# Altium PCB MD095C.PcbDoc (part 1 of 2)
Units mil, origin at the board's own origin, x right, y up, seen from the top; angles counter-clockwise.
Board outline 4500 x 5500 mil, 6 copper layers (Top Layer, Kelvin, MidLayer2, GND, InternalPlane2, Bottom Layer); 145 components, 65 nets, 384 pads, 258 vias.
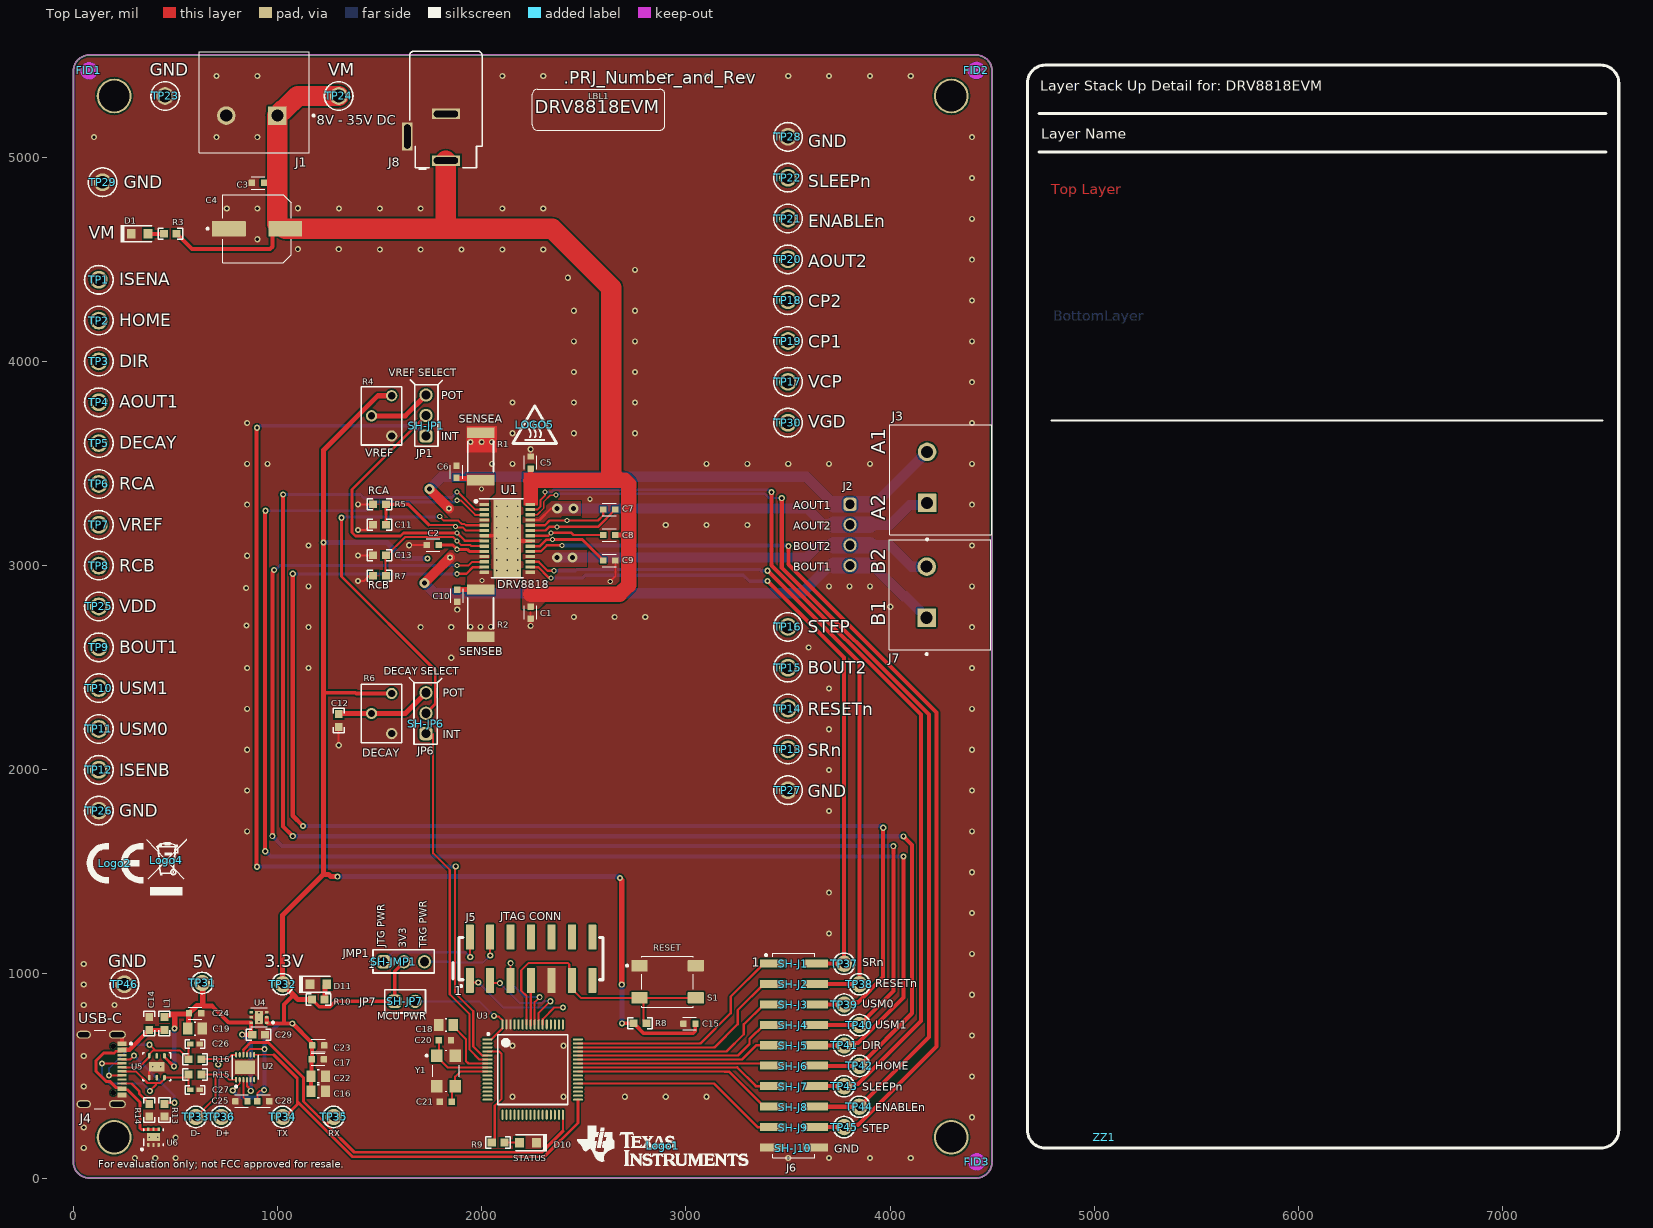
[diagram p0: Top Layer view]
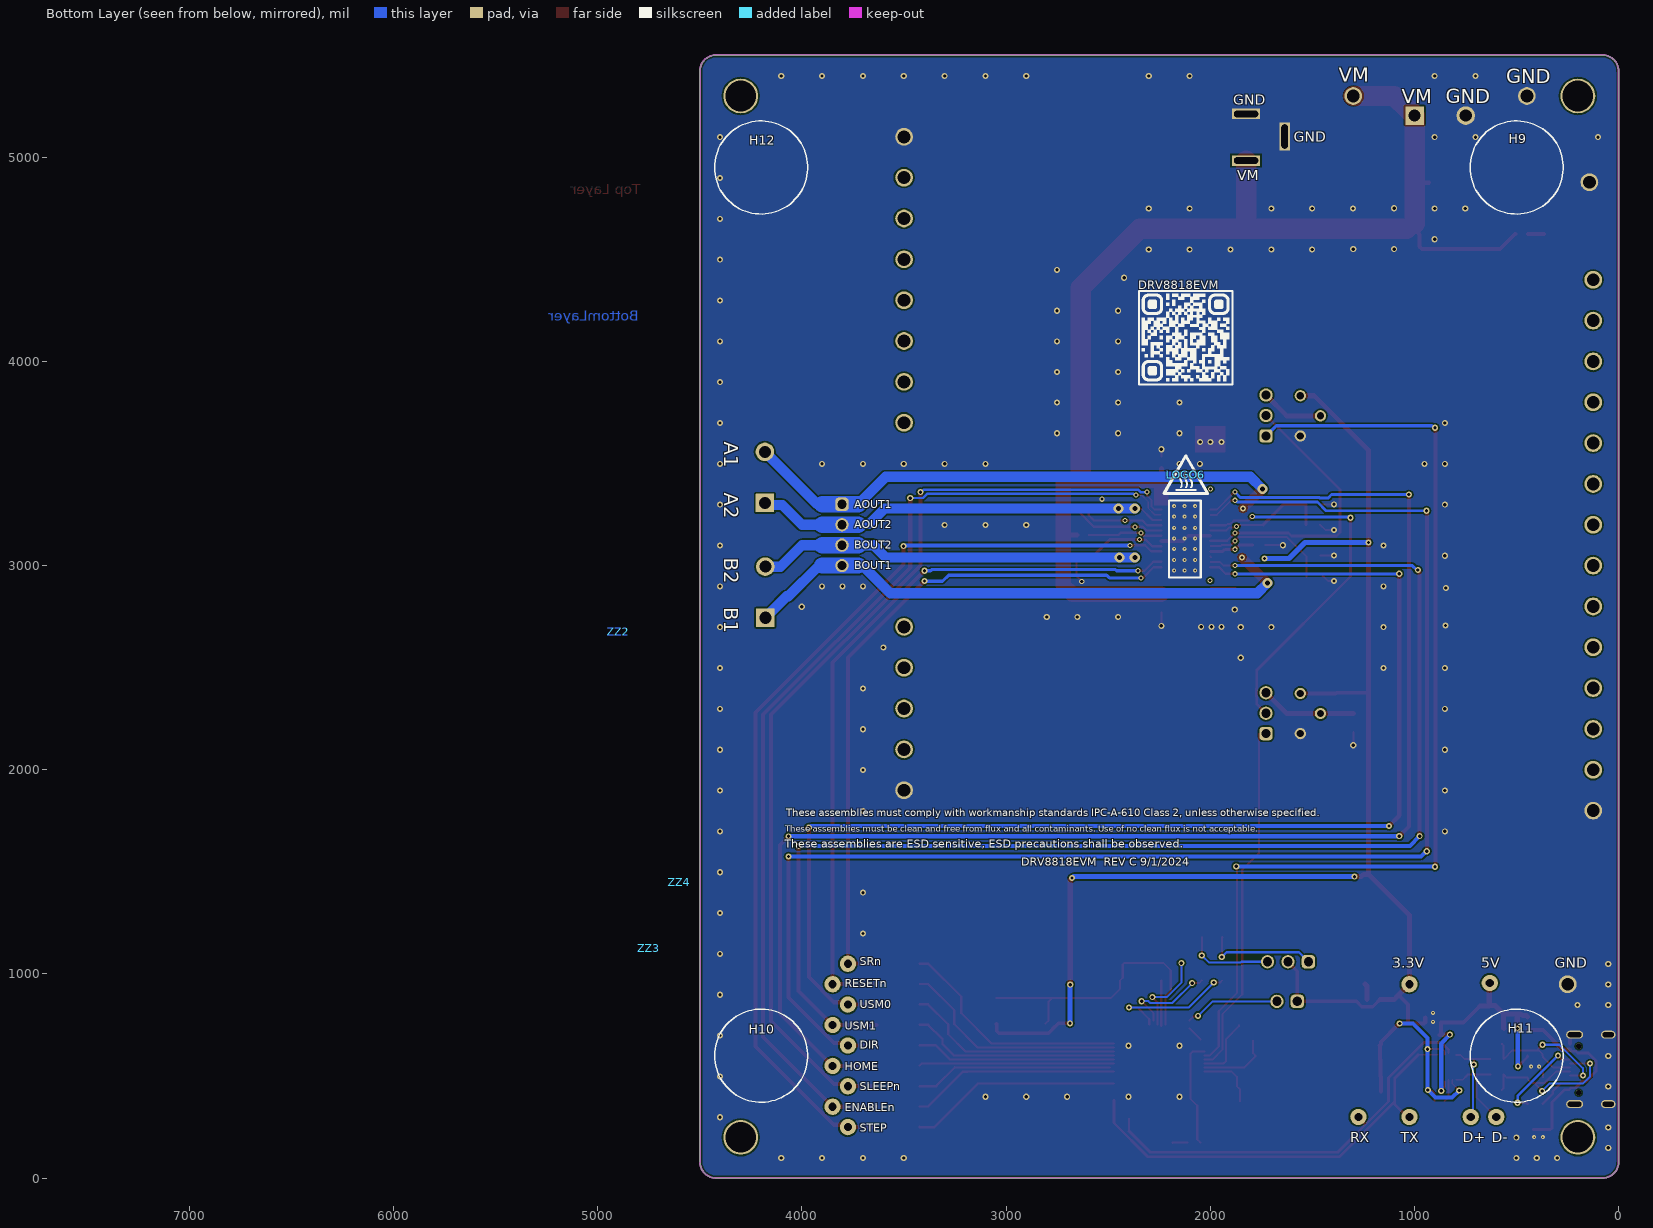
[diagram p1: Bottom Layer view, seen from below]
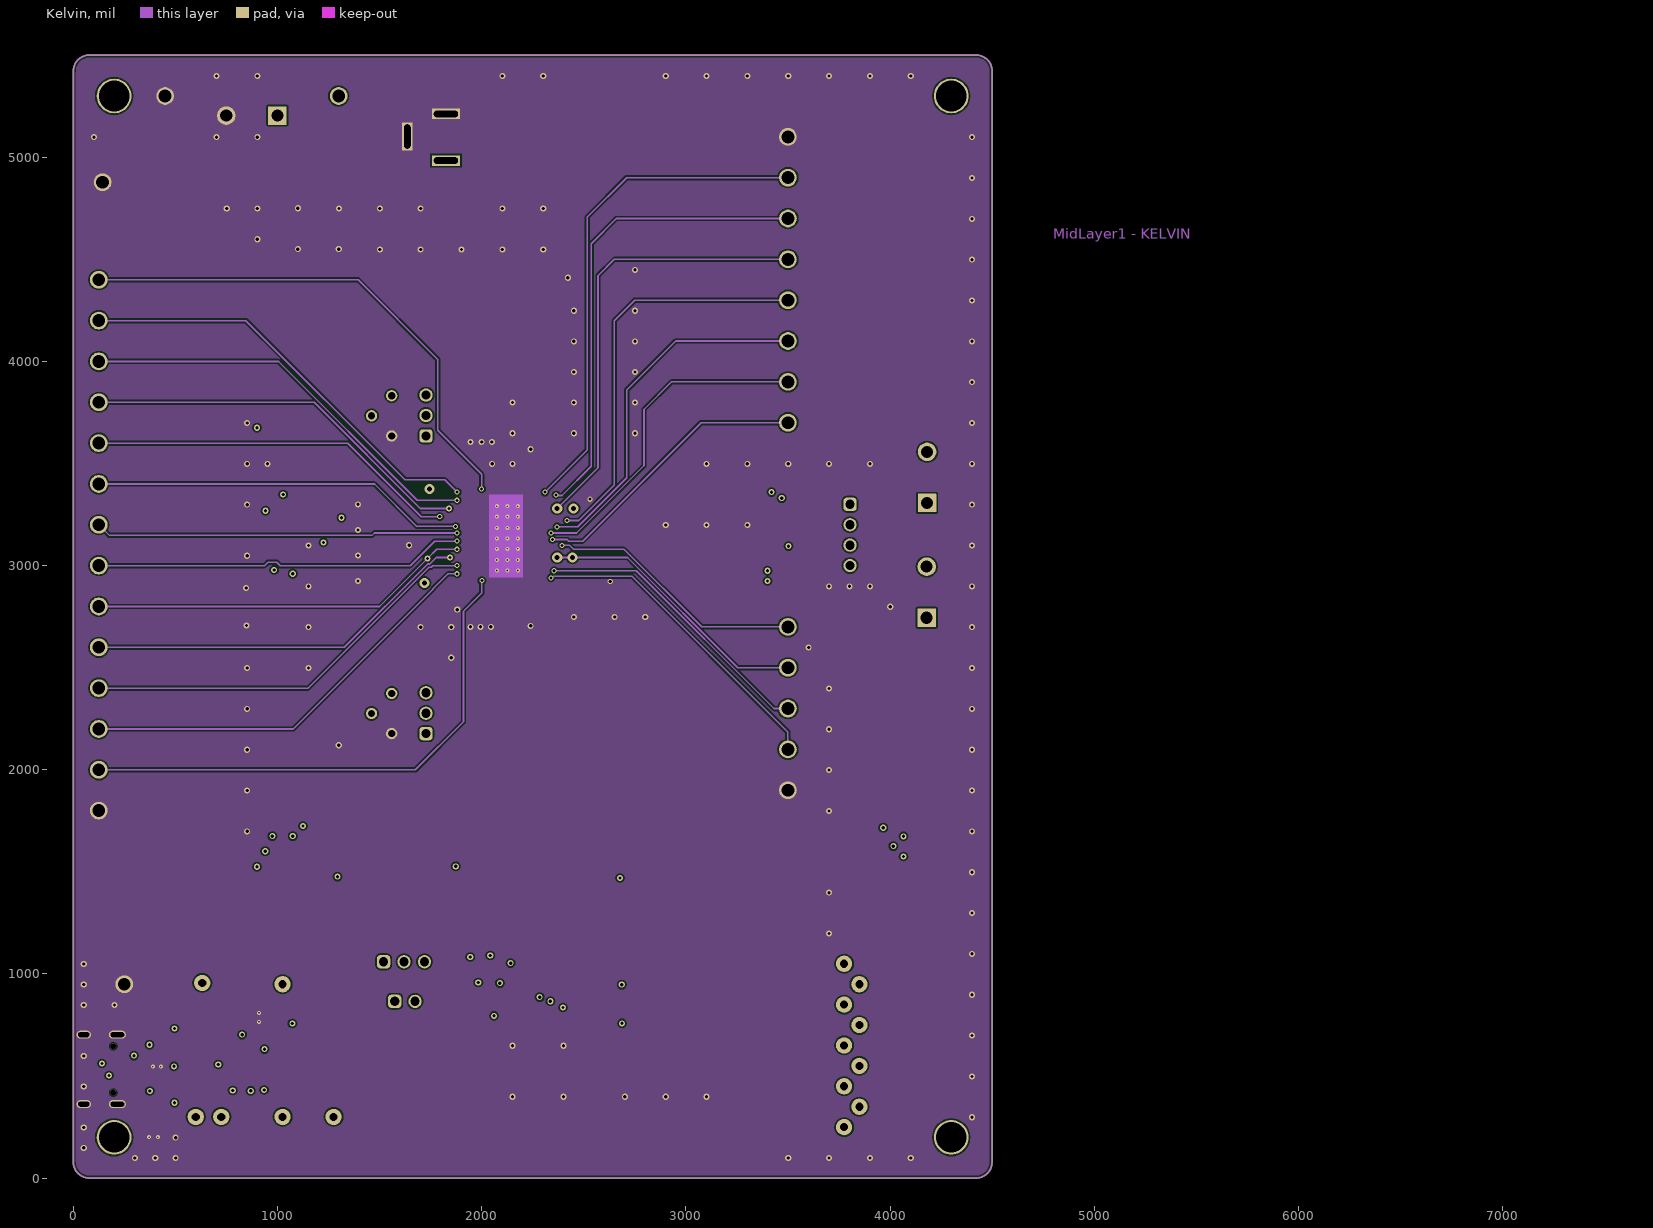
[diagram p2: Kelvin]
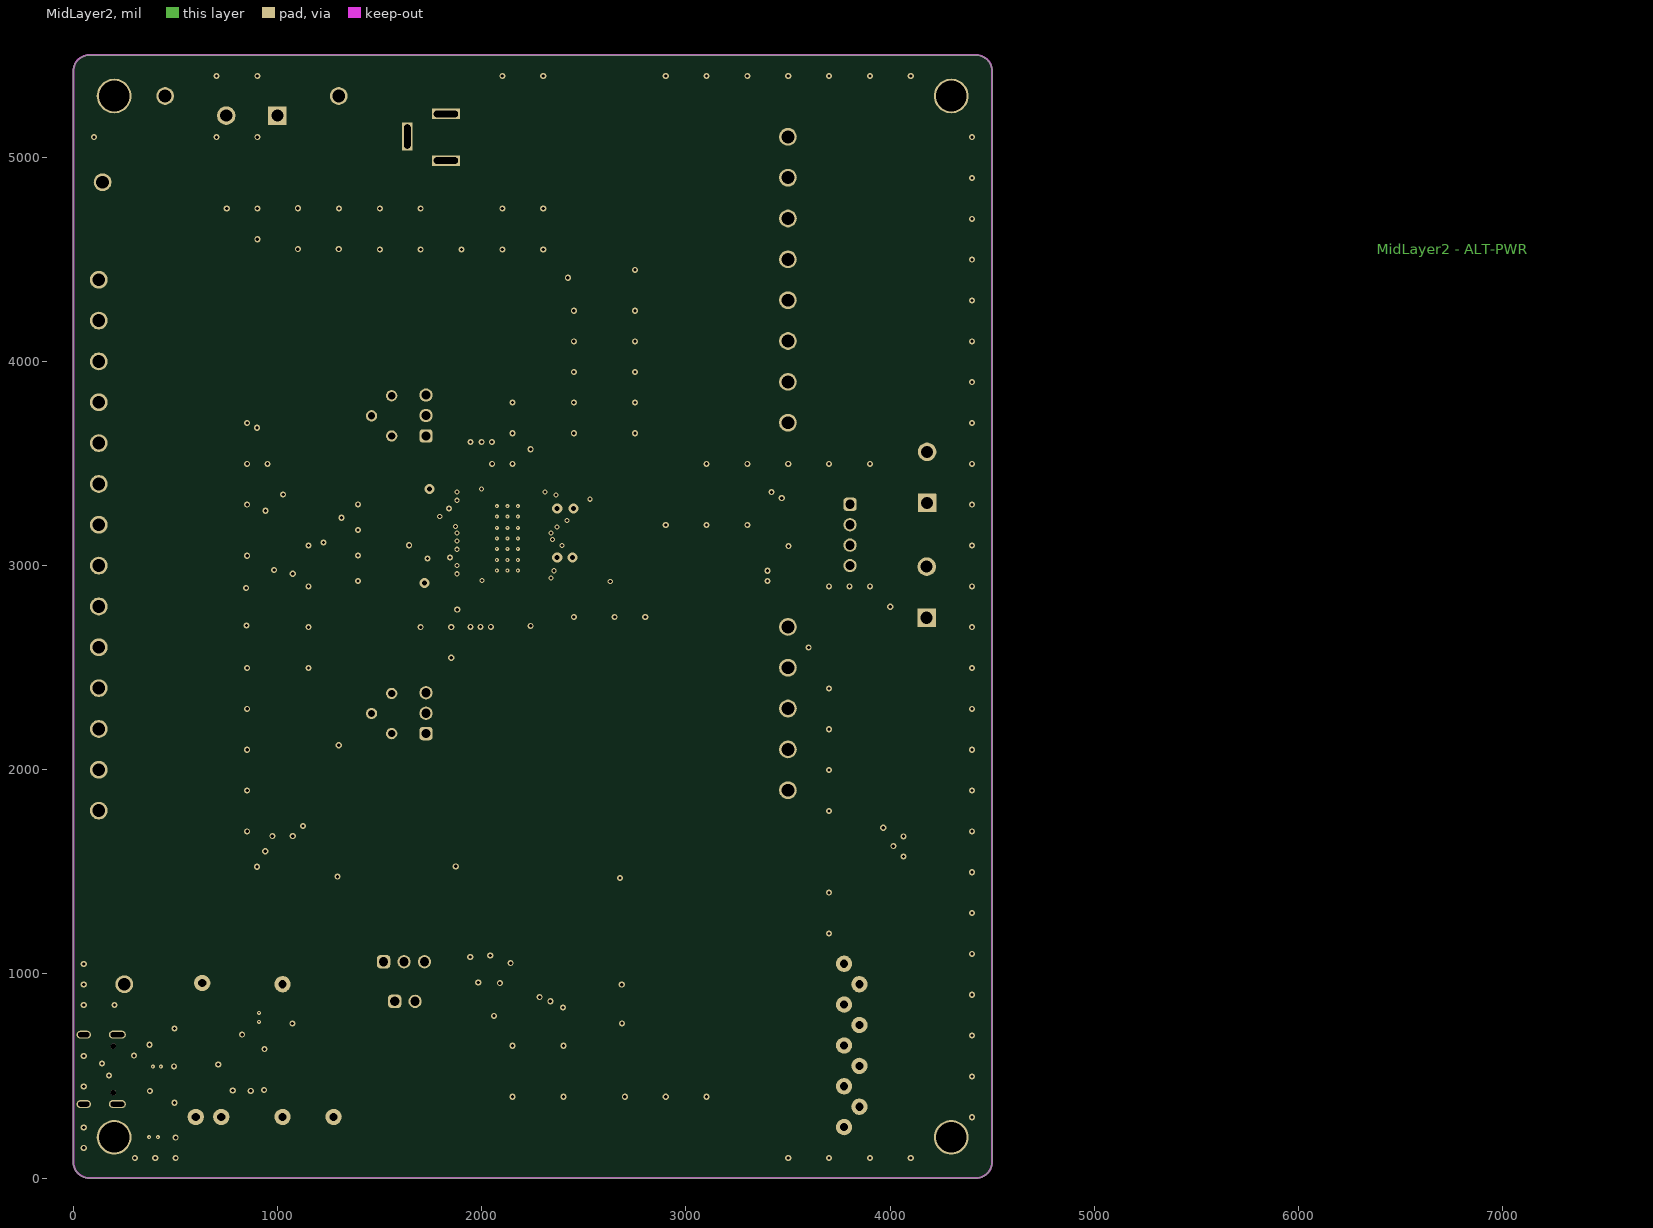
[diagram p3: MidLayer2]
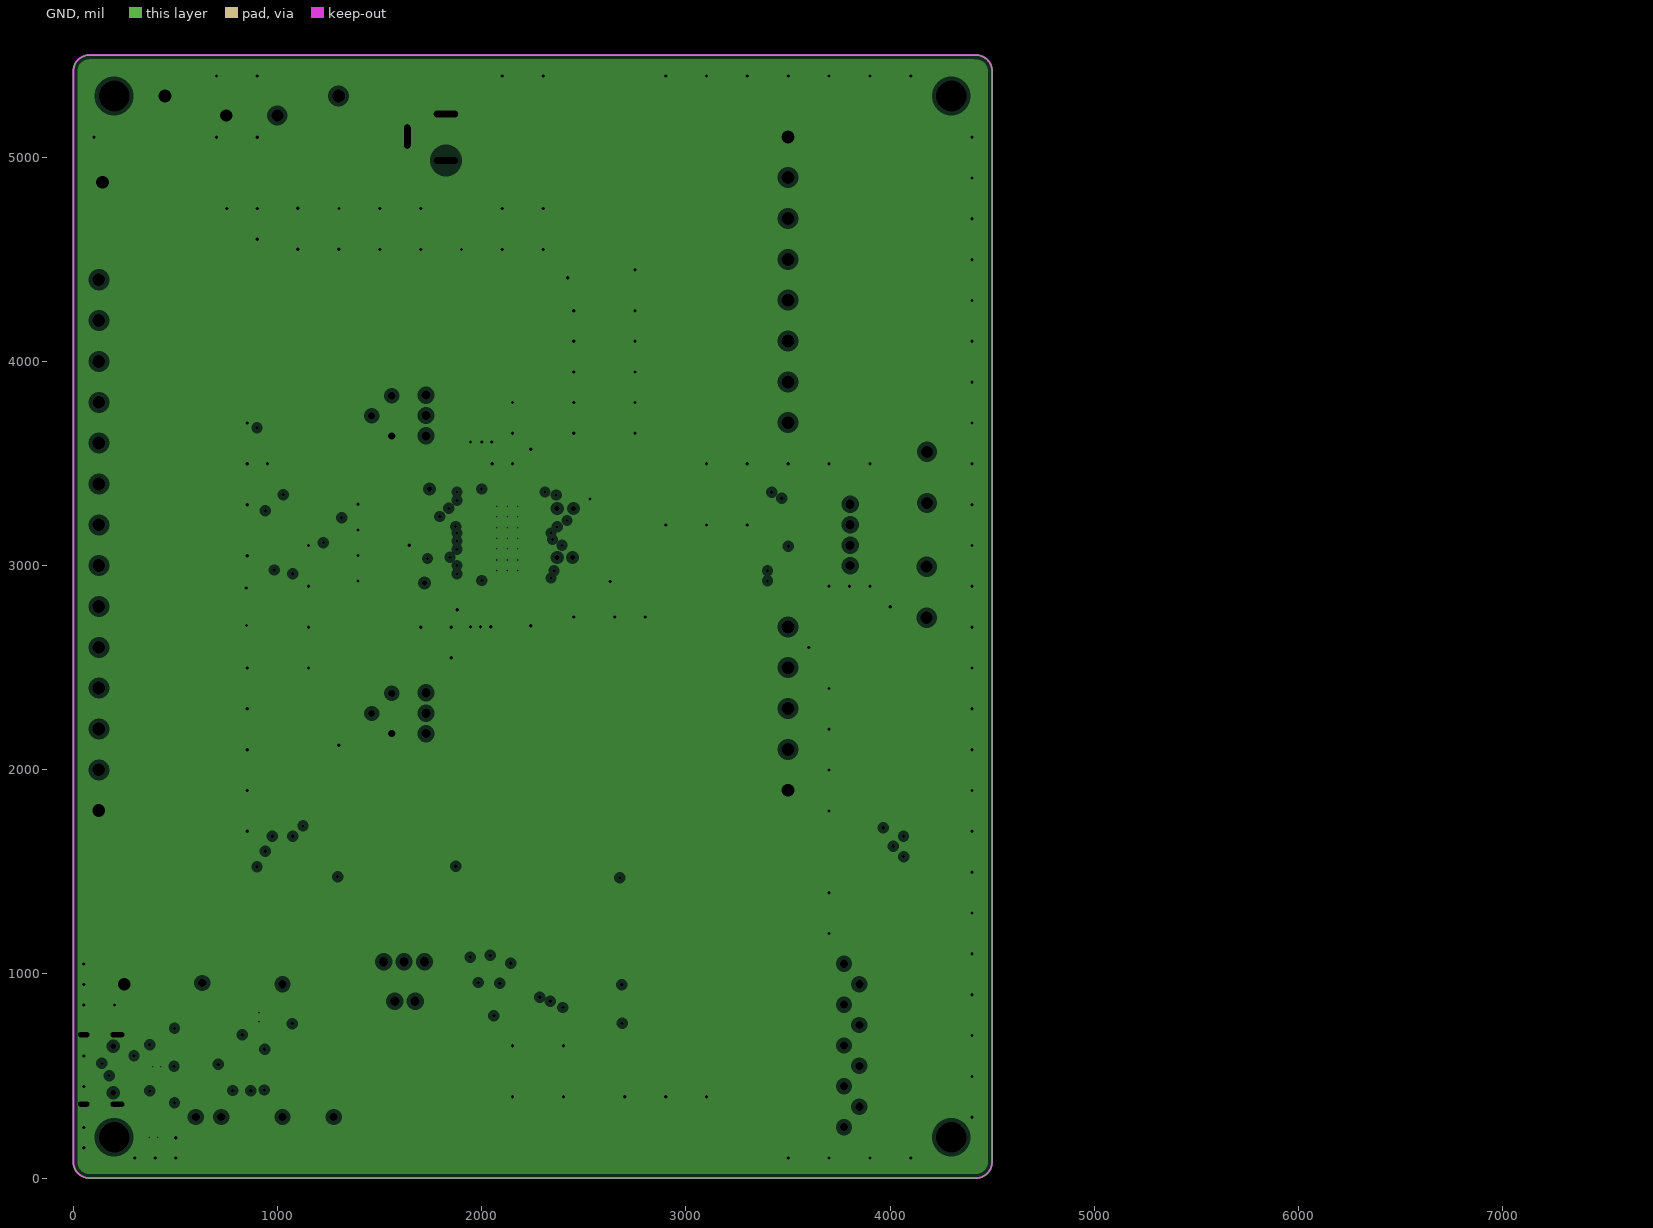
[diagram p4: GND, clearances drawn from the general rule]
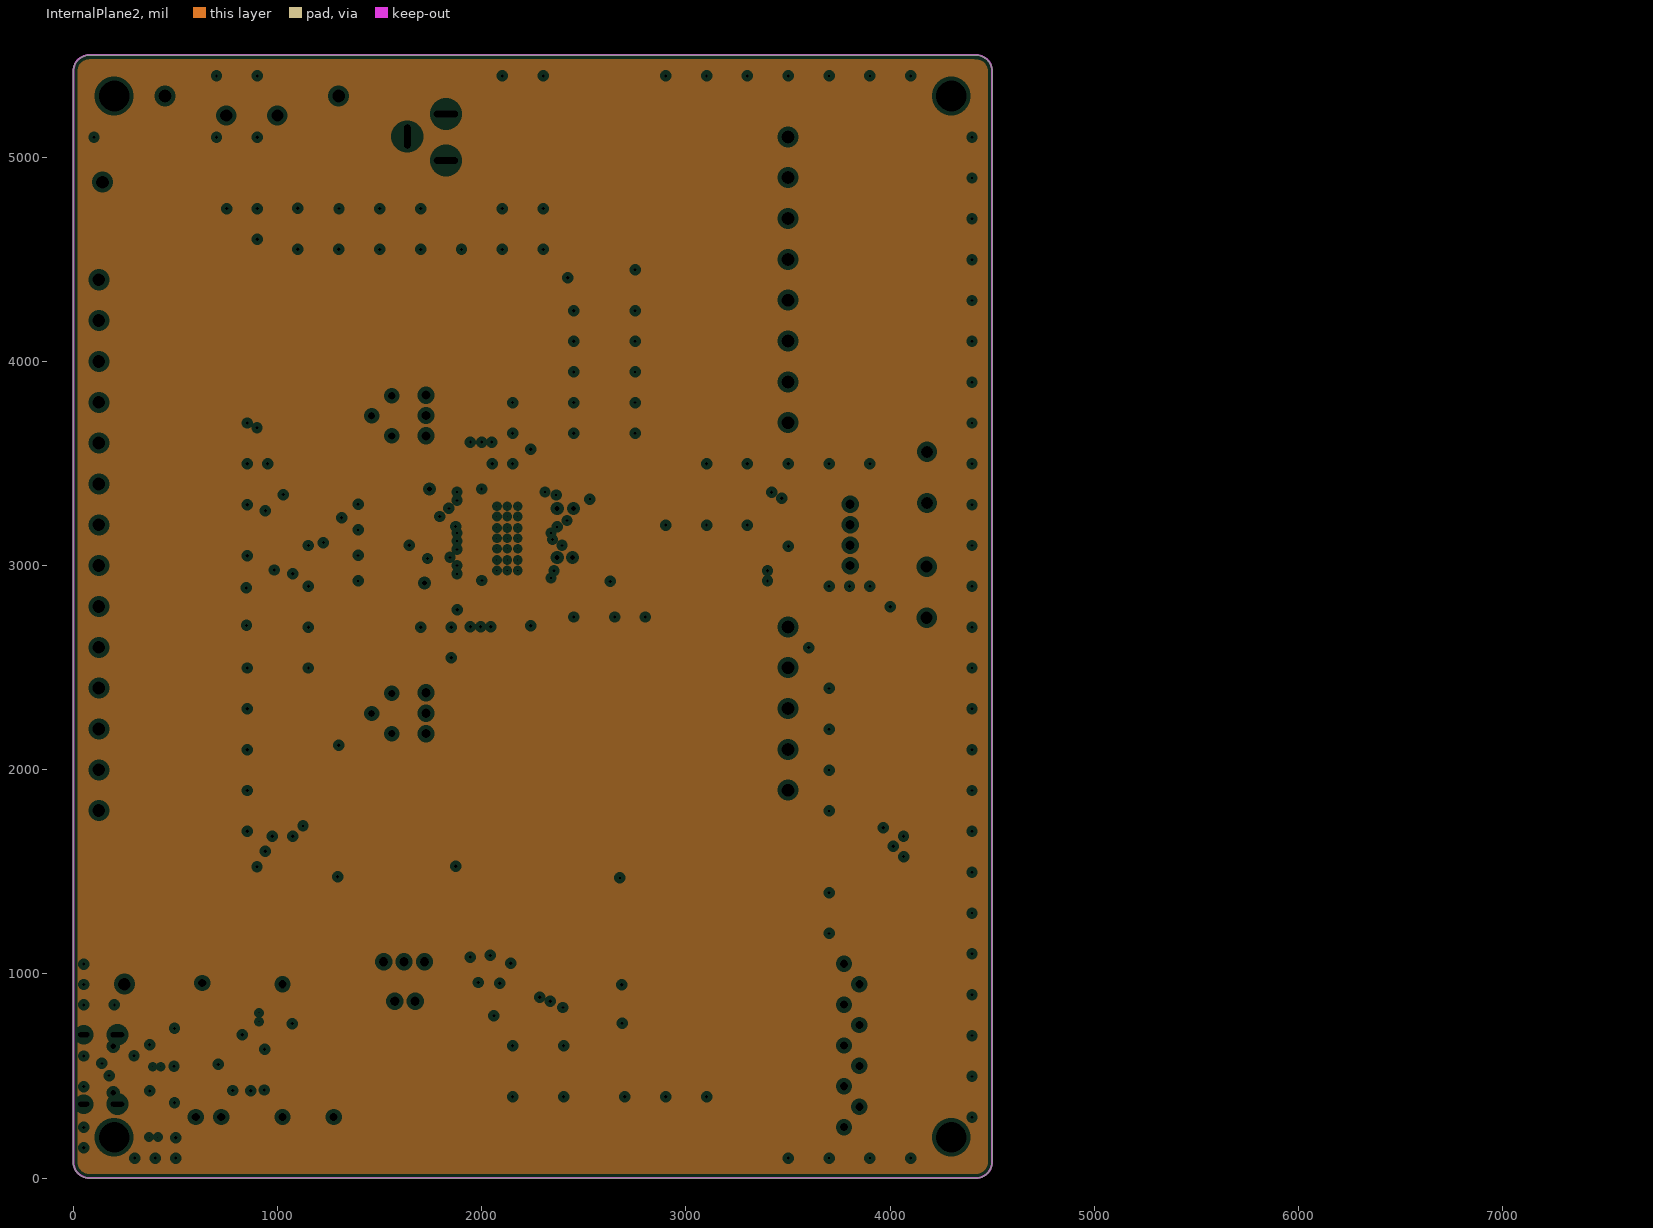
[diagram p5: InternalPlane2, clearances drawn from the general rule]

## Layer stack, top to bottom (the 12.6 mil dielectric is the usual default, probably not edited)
Top Solder: solder mask 0.4, Solder Resist, Dk 3.5
Top Layer: signal copper 1.4
Dielectric1: core 12.6, FR-4, Dk 4.8
Kelvin: signal copper 1.4
Dielectric2: prepreg 12.6, FR-4, Dk 4.8
MidLayer2: signal copper 1.4
Dielectric3: dielectric 12.6, FR-4, Dk 4.8
GND: plane copper 1.4, net GND
Dielectric4: core 12.6, FR-4, Dk 4.8
InternalPlane2: plane copper 1.4
Dielectric5: dielectric 12.6, FR-4, Dk 4.8
Bottom Layer: signal copper 1.4
Bottom Solder: solder mask 0.4, Solder Resist, Dk 3.5

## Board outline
0,79 ccw(c78.74,79) 78.74,0.26 78.74,0 4421,0 4421,0.26 ccw(c4421,79) 4499.74,79 4500,79 4500,5421 ccw(c4421.26,5421) 4421.26,5499.74 4421.26,5500 79,5500 ccw(c79,5421.26) 0.26,5421.26 0,5421.26

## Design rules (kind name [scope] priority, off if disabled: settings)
AssemblyTestPointUsage [All] p1: valid=2
Clearance Clearance_FIDx [InComponent('FID1') or InComponent('FID2') or InComponent('FID3') or InComponent('FID4')] p1: gap=0 ignorepadtopadclearanceinfootprint=TRUE
Clearance Clearance_1 [InNamedPolygon('Top Layer-MGND') Or  InNamedPolygon('Bottom Layer-OD_C_REG') Or  InNamedPolygon('Bottom Layer-OD_A_REG') Or  InNamedPolygon('Bottom Layer-OD_B_REG') Or  InNamedPolygon('Bottom Layer-MGND')] p2: gap=15 ignorepadtopadclearanceinfootprint=TRUE
Clearance [All] p3: gap=7.8 ignorepadtopadclearanceinfootprint=TRUE
ComponentClearance ComponentClearance_Jumpers [InComponent('SH-*')] p1: gap=0 collisioncheckmode=3 verticalgap=0 showdistances=FALSE
ComponentClearance ComponentClearance_MAIN [All] p2: gap=10 collisioncheckmode=3 verticalgap=10 showdistances=FALSE
FabricationTestPointUsage TestPointUsage [All] p1: valid=2 allowmultiple=FALSE
FabricationTestpoint Testpoint [All] p1: side=3 testpointundercomponent=TRUE minsize=40 maxsize=100 preferedsize=60 minholesize=0 maxholesize=40 preferedholesize=32 testpointgrid=1 allowsidetop=TRUE allowsidebottom=TRUE usegrid=TRUE gridtolerance=0.01
HoleSize [All] p1: absolutevalues=TRUE maxlimit=360 minlimit=1 maxpercent=80.000 minpercent=20.000
MinimumAnnularRing [All] p1: minimumring=5
PlaneClearance [All] p1: clearance=20
PlaneConnect [All] p1: planeconnectstyle=Direct reliefexpansion=20 reliefentries=4 reliefconductorwidth=10 reliefairgap=10
PolygonConnect PolygonConnect_2 [(InNet('GND')) vs IsVia  or InComponent('U1')] p1: connectstyle=Direct reliefconductorwidth=10 reliefentries=4 polygonreliefangle="90 Angle" airgapwidth=10
PolygonConnect PolygonConnect_1 [All vs IsNamedPolygon('ISENA') Or  IsNamedPolygon('ISENB') Or  IsNamedPolygon('AOUT2') Or  IsNamedPolygon('BOUT2') Or  IsNamedPolygon('BOUT1') Or  IsNamedPolygon('AOUT1') Or  IsNamedPolygon('VMB') Or  IsNamedPolygon('VMA')] p2: connectstyle=Direct reliefconductorwidth=10 reliefentries=4 polygonreliefangle="90 Angle" airgapwidth=10
PolygonConnect [All] p3: connectstyle=Direct reliefconductorwidth=20 reliefentries=4 polygonreliefangle="90 Angle" airgapwidth=10
RoutingLayers [All] p1: top layer_v5=TRUE mid layer 1_v5=FALSE mid layer 2_v5=FALSE bottom layer_v5=TRUE
RoutingVias [All] p1: holewidth=16 width=30 viastyle="Through Hole" minholewidth=16 minwidth=25 maxholewidth=25 maxwidth=70
SilkToSolderMaskClearance SilkscreenOverComponentPads [IsPad] p1: minsilkscreentomaskgap=10 clearancetoexposedcopper=TRUE
SolderMaskExpansion SolderMaskExpansion_VIAs [IsVia And OnMultiLayer And (AsMils(HoleSize) <= 30     )] p1: expansion=4 istentingtop=TRUE
SupplyNets "Schematic Supply Nets_3" [InNet('VM')] p1: voltage=0.000
SupplyNets "Schematic Supply Nets_2" [InNet('GND')] p2: voltage=0.000
SupplyNets "Schematic Supply Nets_1" [InNet('V3P3')] p3: voltage=0.000
SupplyNets "Schematic Supply Nets" [InNet('5VCC')] p4: voltage=0.000
Width [All] p1: maxlimit=100 minlimit=8 preferedwidth=50 toplayer_prefwidth=10 midlayer1_maxwidth=8 midlayer1_prefwidth=8 midlayer2_maxwidth=8 midlayer2_prefwidth=8 minimp=50.000000 maximp=50.000000 favimp=50.000000
21 further rules are at their usual default settings.

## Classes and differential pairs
component class Header: J2 JMP1 JP1 JP6 JP7
component class Shunt: SH-J1 SH-J2 SH-J3 SH-J4 SH-J5 SH-J6 SH-J7 SH-J8 SH-J9 SH-J10 SH-JMP1 SH-JP1 SH-JP6 SH-JP7
component class MD095C: C1 C2 C3 C4 C5 C6 C7 C8 C9 C10 C11 C12 C13 D1 J1 J2 J3 J7 J8 JP1 JP6 R1 R2 R3 R4 R5 R6 R7 SH-JP1 SH-JP6 SHNT1 SHNT2 SHNT3 SHNT4 SHNT5 SHNT6 TP1 TP2 TP3 TP4 TP5 TP6 TP7 TP8 TP9 TP10 TP11 TP12 TP13 TP14 TP15 TP16 TP17 TP18 TP19 TP20 TP21 TP22 TP23 TP24 TP25 TP26 TP27 TP28 TP29 TP30 U1
component class MD095C_MSP430: C14 C15 C16 C17 C18 C19 C20 C21 C22 C23 C24 C25 C26 C27 C28 C29 D10 D11 J4 J5 J6 JMP1 JP7 L1 R8 R9 R10 R13 R14 R15 R16 S1 SH-J1 SH-J2 SH-J3 SH-J4 SH-J5 SH-J6 SH-J7 SH-J8 SH-J9 SH-J10 SH-JMP1 SH-JP7 SHNT7 SHNT8 TP31 TP32 TP33 TP34 TP35 TP36 TP37 TP38 TP39 TP40 TP41 TP42 TP43 TP44 TP45 TP46 U2 U3 U4 U5 U6 Y1
component class MD095C_Hardware: !PCB FID1 FID2 FID3 H9 H10 H11 H12 LBL1 Logo1 Logo2 Logo3 Logo4 LOGO5 LOGO6 ZZ1 ZZ2 ZZ3 ZZ4
component class Logo: Logo1
component class Label: LBL1
component class FiducialMark: FID1 FID2 FID3
component class AssemblyNote: ZZ1 ZZ2 ZZ3 ZZ4
polygon class PinPolygons: Bottom-GND VDD

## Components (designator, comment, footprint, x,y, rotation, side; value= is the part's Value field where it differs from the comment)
C1 "885012206095" FP-885012206095_0603-MFG 2240,2770 r90 top value=100nF
C2 "885012206095" FP-885012206095_0603-MFG 1761,3101 r0 top value=100nF
C3 "885012206095" FP-885012206095_0603-MFG 904.53,4875 r0 top value=100nF
C4 "865080653016" FP-865080653016_SMT_CAP_8MM3_8MM3-MFG 900,4650 r0 top value=100µF
C5 "885012206095" FP-885012206095_0603-MFG 2240,3505 r270 top value=100nF
C6 "885012206095" FP-885012206095_0603-MFG 1876.74,3458.96 r90 top value=100nF
C7 "885012206125" FP-885012206125_0603-MFG 2625,3275 r0 top value=220nF
C8 "885012206125" FP-885012206125_0603-MFG 2625,3150 r180 top value=220nF
C9 "885012206125" FP-885012206125_0603-MFG 2625,3025 r0 top value=220nF
C10 "885012206095" FP-885012206095_0603-MFG 1880.11,2852.63 r270 top value=100nF
C11 "885012206083" 0603 1500,3200 r180 top value=1000pF
C12 "885012206083" 0603 1300,2242 r270 top value=1000pF
C13 "885012206083" 0603 1500,3050 r180 top value=1000pF
C14 "885012206089" 0603 371.5,757.69 r90 top value=0.01uF
C15 "885012206095" FP-885012206095_0603-MFG 3018,757 r180 top value=100nF
C16 "885012107014" 0805_150 1200,425 r0 top value=10uF
C17 "885012206095" FP-885012206095_0603-MFG 1198.16,582.38 r180 top value=100nF
C18 "885012107014" 0805_150 1825,750 r180 top value=10uF
C19 "885012107014" 0805_150 596.5,732.69 r0 top value=10uF
C20 "885012006054" WCAP-CSGP_0603_L1.6W0.8H0.8_Reflow 1820.47,675 r180 top value=33pF
C21 "885012006054" WCAP-CSGP_0603_L1.6W0.8H0.8_Reflow 1825,375 r0 top value=33pF
C22 "885012107014" 0805_150 1200,500 r0 top value=10uF
C23 "885012206095" FP-885012206095_0603-MFG 1200,650 r180 top value=100nF
C24 "885012206095" FP-885012206095_0603-MFG 596.5,807.69 r0 top value=100nF
C25 "885012206095" FP-885012206095_0603-MFG 823.79,376.93 r0 top value=100nF
C26 "885012005044" 0402 596.5,657.69 r0 top value=47pF
C27 "885012005044" 0402 596.5,432.69 r0 top value=47pF
C28 "885012206095" FP-885012206095_0603-MFG 931.11,376.93 r0 top value=100nF
C29 "885012106017" 0603 908,702 r180 top value=1uF
D1 "150080RS75000" WL-SMCW_RED_0805 325,4625 r0 top value=Red
D10 "150080RS75000" WL-SMCW_RED_0805 2226.66,173 r180 top value=Red
D11 "150080RS75000" WL-SMCW_RED_0805 1200,950 r0 top value=Red
FID1 "Fiducial" Fiducial10-20#1 77,5423 r0 top
FID2 "Fiducial" Fiducial10-20#2 4423,5425 r0 top
FID3 "Fiducial" Fiducial10-20#2 4425,80 r0 top
H9 "SJ-5303 (CLEAR)" Bumpon_SJ5003Transparent 500,4950 r180 bottom
H10 "SJ-5303 (CLEAR)" Bumpon_SJ5003Transparent 4200,600 r180 bottom
H11 "SJ-5303 (CLEAR)" Bumpon_SJ5003Transparent 500,600 r180 bottom
H12 "SJ-5303 (CLEAR)" Bumpon_SJ5003Transparent 4200,4950 r180 bottom
J1 "691250610002" FP-691250610002_CONN_TERM_BLOCK2-MFG 886,5269 r180 top
J2 "61300411121" WURTH_61300411121 3804.37,3150.26 r270 top
J3 "691250610002" FP-691250610002_CONN_TERM_BLOCK2-MFG 4246.68,3420.39 r90 top
J4 "629722000214" FP-629722000214_CONN_USB-MFG 96.5,532.69 r270 top
J5 "61031421121" FP-61031421121_HDR14-MFG 2242,1074.7 r0 top
J6 "61032021121" FP-61032021121_HDR20-MFG 3529.7,601 r270 top locked
J7 "691250610002" FP-691250610002_CONN_TERM_BLOCK2-MFG 4244.75,2858 r90 top
J8 "694106301002" Wurth_694106301002 1825,5097.83 r0 top
JMP1 "61300311121" WURTH_61300311121 1620,1060 r0 top
JP1 "61300311121" WURTH_61300311121 1727.57,3735.19 r90 top
JP6 "61300311121" WURTH_61300311121 1727.57,2277.2 r90 top
JP7 "61300211121" WURTH_61300211121 1624,866 r0 top
L1 "742863160" 0603 446.5,757.69 r90 top value="600 ohm"
LBL1 "THT-14-423-10" Label_650x200 2573,5233 r180 top
Logo1 "Texas Instruments" TI_Stacked_Overlay_Small 2887,159 r0 top
Logo2 "CE Mark" CE_Mark_5mm 204,1543 r0 top
Logo3 "FCC disclaimer" FCC_disclaimer 948.99,6251 r0 top
Logo4 "WEEE logo" WEEE_Minimum 456,1557 r0 top
LOGO5 "CAUTION HOT SURFACE" IEC_HotSurface_Small 2260,3691 r0 top
LOGO6 "CAUTION HOT SURFACE" IEC_HotSurface_Small 2120,3446 r180 bottom
R1 "CRA2512-FZ-R100ELF" 2512 1995,3535 r90 top value=0.1
R2 "CRA2512-FZ-R100ELF" 2512 1995,2767 r270 top value=0.1
R3 "RC0603FR-074K7L" 0603 475,4625 r180 top value=4.70k
R4 "PV37W502C01B00" Bourns_PV37W 1510.27,3733.63 r180 top value="5k Ohm"
R5 "RC0603FR-0747KL" 0603 1500,3300 r0 top value=47.0k
R6 "PV37W502C01B00" Bourns_PV37W 1510.27,2275.64 r180 top value="5k Ohm"
R7 "RC0603FR-0747KL" 0603 1500,2950 r0 top value=47.0k
R8 "RC0603FR-074K7L" 0603 2776,758 r0 top value=4.70k
R9 "RC0603FR-071KL" 0603 2081,175 r180 top value=1.00k
R10 "RC0603FR-071KL" 0603 1200,875 r180 top value=1.00k
R13 "RC0603JR-075K1L" 0603 446.5,332.69 r270 top value=5.1k
R14 "RC0603JR-075K1L" 0603 371.5,332.69 r270 top value=5.1k
R15 "CRCW060327R0JNEA" 0603 596.5,507.69 r0 top value=27
R16 "CRCW060327R0JNEA" 0603 596.5,582.69 r0 top value=27
S1 "430481025816" FP-430481025816_SMT_SW_6MM2_6MM2-MFG 2911,962 r0 top
SH-J1 "60900213421" Wurth_60900213421 3527,1050 r180 top
SH-J2 "60900213421" Wurth_60900213421 3527,949.62 r180 top
SH-J3 "60900213421" Wurth_60900213421 3527,849.25 r180 top
SH-J4 "60900213421" Wurth_60900213421 3527,748.88 r180 top
SH-J5 "60900213421" Wurth_60900213421 3527,648.5 r180 top
SH-J6 "60900213421" Wurth_60900213421 3527,548.12 r180 top
SH-J7 "60900213421" Wurth_60900213421 3527,447.75 r180 top
SH-J8 "60900213421" Wurth_60900213421 3527,347.38 r180 top
SH-J9 "60900213421" Wurth_60900213421 3527,247 r180 top
SH-J10 "60900213421" Wurth_60900213421 3527,147 r180 top
SH-JMP1 "60900213421" Wurth_60900213421 1569,1061 r180 top
SH-JP1 "60900213421" Wurth_60900213421 1728,3684 r90 top
SH-JP6 "60900213421" Wurth_60900213421 1726,2226 r90 top
SH-JP7 "60900213421" Wurth_60900213421 1623,867 r180 top
TP1 "ISENA" Keystone5012 125,4400 r90 top
TP2 "HOME" Keystone5012 125,4200 r90 top
TP3 "DIR" Keystone5012 125,4000 r90 top
TP4 "AOUT1" Keystone5012 125,3800 r90 top
TP5 "DECAY" Keystone5012 125,3600 r90 top
TP6 "RCA" Keystone5012 125,3400 r90 top
TP7 "VREF" Keystone5012 125,3200 r90 top
TP8 "RCB" Keystone5012 125,3000 r90 top
TP9 "BOUT1" Keystone5012 125,2600 r90 top
TP10 "USM1" Keystone5012 125,2400 r90 top
TP11 "USM0" Keystone5012 125,2200 r90 top
TP12 "ISENB" Keystone5012 125,2000 r90 top
TP13 "SRn" Keystone5012 3500,2100 r90 top
TP14 "RESETn" Keystone5012 3500,2300 r90 top
TP15 "BOUT2" Keystone5012 3500,2500 r90 top
TP16 "STEP" Keystone5012 3500,2700 r90 top
TP17 "VCP" Keystone5012 3500,3900 r90 top
TP18 "CP2" Keystone5012 3500,4300 r90 top
TP19 "CP1" Keystone5012 3500,4100 r90 top
TP20 "AOUT2" Keystone5012 3500,4500 r90 top
TP21 "ENABLEn" Keystone5012 3500,4700 r90 top
TP22 "SLEEPn" Keystone5012 3500,4900 r90 top
TP23 "GND" Keystone5011 450,5300 r90 top
TP24 "VM" Keystone5010 1300,5300 r90 top
TP25 "VDD" Keystone5010 125,2800 r90 top
TP26 "GND" Keystone5011 125,1800 r90 top
TP27 "GND" Keystone5011 3500,1900 r90 top
TP28 "GND" Keystone5011 3500,5100 r90 top
TP29 "GND" Keystone5011 143.48,4877.7 r90 top
TP30 "VGD" Keystone5012 3500,3700 r90 top
TP31 "5V" Keystone5003 631.33,956.04 r90 top
TP32 "3.3V" Keystone5003 1025,950 r90 top
TP33 "D-" Keystone5002 600,300 r90 top
TP34 "TX" Keystone5002 1025,300 r90 top
TP35 "RX" Keystone5002 1275,300 r90 top
TP36 "D+" Keystone5002 725,300 r90 top
TP37 "5002" Keystone5002 3775,1050 r90 top
TP38 "5002" Keystone5002 3850,950 r90 top
TP39 "5002" Keystone5002 3775,850 r90 top
TP40 "5002" Keystone5002 3850,750 r90 top
TP41 "5002" Keystone5002 3775,650 r90 top
TP42 "5002" Keystone5002 3850,550 r90 top
TP43 "5002" Keystone5002 3775,450 r90 top
TP44 "5002" Keystone5002 3850,350 r90 top
TP45 "5002" Keystone5002 3775,250 r90 top
TP46 "GND" Keystone5011 250,950 r90 top
U1 "DRV8818PWP" PWP0028D_L 2125.8,3133.66 r0 top
U2 "FT234XD-R" FP-FT234XD-R_DFN-12-MFG 841.92,543.36 r90 top
U3 "MSP430F2617TPM" PM0064A_L 2250,532 r0 top
U4 "TLV76733DRVT" DRV0006A-MFG 909.39,787.59 r180 top
U5 "TPD2E001DRSR" DRS0006A 409.1,545.83 r270 top
U6 "TVS0500DRVR" DRV0006A 393,201 r90 top
Y1 "830055663" FP-830055663_SMT_CRYSTAL_5MM0_3MM2-MFG 1825,525 r270 top
ZZ1 "This Assembly Note is for PCB labels only" AssemblyNoteLabel 5050,200 r90 top
ZZ2 "These assemblies are ESD sensitive, ESD precautions shall be observed." AssemblyNote 4900,2675 r90 bottom
ZZ3 "These assemblies must be clean and free from flux and all contaminants. Use of no clean flux is not acceptable." AssemblyNote 4750,1125 r90 bottom
ZZ4 "These assemblies must comply with workmanship standards IPC-A-610 Class 2, unless otherwise specified." AssemblyNote 4600,1450 r90 bottom

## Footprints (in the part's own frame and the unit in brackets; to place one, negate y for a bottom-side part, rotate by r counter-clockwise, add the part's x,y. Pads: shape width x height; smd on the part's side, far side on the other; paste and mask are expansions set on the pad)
0402 [mm] "0402 from SM-752 data"
  rect 0.8x0.6 smd: 1(-0.6,0) 2(0.6,0)
  silkscreen extent -1.22,-0.52 1.22,0.52, body extent -0.55,-0.3 0.55,0.3, height 0.6
0603 [mm] "0603 from SM-752 data"
  rect 1x0.95 smd: 1(-0.8,0) 2(0.8,0)
  silkscreen extent -1.52,-0.69 1.52,0.69, body extent -0.87,-0.47 0.87,0.47, height 1
0805_150 [mm] "0805 / 1.5 mm height"
  rect 1.15x1.45 smd: 1(-0.9,0) 2(0.9,0)
  silkscreen extent -0.1,-0.8 0.1,0.8, body extent -1.1,-0.72 1.1,0.72, height 1.5
2512 [mm] "Chip Resistor, Body 6.3x3.2mm, IPC Medium Density"
  rect 1.3x3.4 smd: 1(-2.95,0) 2(2.95,0)
  silkscreen extent -1.9,-1.6 1.9,1.6, body extent -3.22,-1.67 3.22,1.67, height 0.71
AssemblyNote [mil] "Assembly Note"
AssemblyNoteLabel [mil] "Assembly Note for PCB Labels"
Bourns_PV37W [mm] "TH, 3-Leads, Body 6.71x4.5mm"
  round 1.4 hole 0.9: 1(-1.25,2.5) 2(1.25,0) 3(-1.25,-2.5)
  silkscreen extent -2.52,-3.63 2.52,3.63, body extent -2.44,-3.54 2.44,3.54, height 8.39
Bumpon_SJ5003Transparent [mil] "3M Hemispherical Bumpon transparent"
  round 1 on Mech3: 0(0,0)
  silkscreen extent -228,-228 228,228, body extent -218,-218 219,218, height 197
CE_Mark_5mm [mil] "Minimum text height for CE Mark"
  silkscreen extent -138,-98 138,98
DRS0006A [mm] "SON, 6-Leads, Body 3x3mm, Pitch 0.95mm, Thermal Pad 2x1.3mm, TI Recommended"
  rrect100% 0.7x0.35 smd: 1(-1.35,0.95) 2(-1.35,0) 3(-1.35,-0.95) 4(1.35,-0.95) 5(1.35,0) 6(1.35,0.95)
  rrect9% 1.126x1.71 on Top Paste: 7(0,0)
  rrect8% 1.2x1.9 smd paste-0.6: 7(0,0)
  silkscreen extent -1.73,-1.73 1.72,1.73, body extent -1.58,-1.57 1.57,1.58, height 0.81
DRV0006A [mm] "SON, 6-Leads, Body 2x2mm, Pitch 0.65mm, Thermal Pad 1.6x1mm, TI Recommended"
  rrect33% 0.45x0.3 smd: 1(-0.975,0.65) 2(-0.975,0) 3(-0.975,-0.65) 4(0.975,-0.65) 5(0.975,0) 6(0.975,0.65)
  rrect14% 1x0.7 on Top Paste: 7(0,0.45) 7(0,-0.45)
  rrect10% 1x1.6 smd paste-0.5: 7(0,0)
  silkscreen extent -1.05,-1.2 1.05,1.2, body extent -1.05,-1.05 1.05,1.05, height 0.81
DRV0006A-MFG [mm]
  rrect33% 0.45x0.3 smd paste+0 mask+0: 1(-0.975,0.65) 2(-0.975,0) 3(-0.975,-0.65) 4(0.975,-0.65) 5(0.975,0) 6(0.975,0.65)
  rrect10% 1x1.6 smd paste-1000 mask+0: 7(0,0)
  silkscreen extent -1.88,-1.18 1.05,1.17, body extent -1.3,-1.15 1.3,1.15, height 0.25
FCC_disclaimer [mil]
Fiducial10-20#1 [mm]
  round 1 smd mask+0.5: 1(0,0.051)
  Top Layer keep-out circle w1.178: c0,0 r0.5
Fiducial10-20#2 [mm]
  round 1 smd mask+0.5: 1(0,0)
  Top Layer keep-out circle w1.178: c0,0 r0.5
FP-830055663_SMT_CRYSTAL_5MM0_3MM2-MFG [mm]
  rrect7% 1.6x1.4 smd paste+0 mask+0: 1(-1.9,-1.15) 2(1.9,-1.15) 3(1.9,1.15) 4(-1.9,1.15)
  silkscreen extent -2.55,-2.52 2.55,1.65, body extent -2.8,-1.95 2.8,1.95, height 0.25
FP-61031421121_HDR14-MFG [mm]
  rrect10% 1x3.1 smd paste+0 mask+0: 1(-7.62,-2.7) 2(-7.62,2.7) 3(-5.08,-2.7) 4(-5.08,2.7) 5(-2.54,-2.7) 6(-2.54,2.7) 7(0,-2.7) 8(0,2.7) 9(2.54,-2.7) 10(2.54,2.7) 11(5.08,-2.7) 12(5.08,2.7) 13(7.62,-2.7) 14(7.62,2.7)
  silkscreen extent -8.97,-3.52 8.97,2.62, body extent -9.07,-4.35 9.07,4.35, height 0.25
FP-61032021121_HDR20-MFG [mm]
  rrect10% 1x3.1 smd paste+0 mask+0: 1(-11.43,-2.7) 2(-11.43,2.7) 3(-8.89,-2.7) 4(-8.89,2.7) 5(-6.35,-2.7) 6(-6.35,2.7) 7(-3.81,-2.7) 8(-3.81,2.7) 9(-1.27,-2.7) 10(-1.27,2.7) 11(1.27,-2.7) 12(1.27,2.7) 13(3.81,-2.7) 14(3.81,2.7) 15(6.35,-2.7) 16(6.35,2.7) 17(8.89,-2.7) 18(8.89,2.7) 19(11.43,-2.7) 20(11.43,2.7)
  silkscreen extent -12.7,-3.6 12.7,2.62, body extent -12.8,-4.35 12.8,4.35, height 0.25
FP-430481025816_SMT_SW_6MM2_6MM2-MFG [mm]
  rrect7% 2x1.4 smd paste+0 mask+0: 1(-3.5,2) 2(3.5,2) 3(-3.5,-2) 4(3.5,-2)
  silkscreen extent -5.17,-3.2 3.2,3.2, body extent -4.6,-3.3 4.6,3.3, height 0.25
FP-629722000214_CONN_USB-MFG [mm]
  rrect100% 1x2.1 hole 1.7 slot 0.6 at 0 deg paste-2539.97 mask+0: 1(-4.32,3.035) 2(4.32,3.035)
  rrect100% 1x1.8 hole 1.4 slot 0.6 at 0 deg paste-2539.97 mask+0: 3(-4.32,-1.145) 4(4.32,-1.145)
  rrect17% 0.6x1.15 smd paste+0 mask+0: A1-B12(-3.2,3.6) A4-B9(-2.4,3.6) A9-B4(2.4,3.6) A12-B1(3.2,3.6)
  rrect33% 0.3x1.15 smd paste+0 mask+0: A5(-1.25,3.6) A6(-0.25,3.6) A7(0.25,3.6) A8(1.25,3.6) B5(1.75,3.6) B6(0.75,3.6) B7(-0.75,3.6) B8(-1.75,3.6)
  round 0.65 hole 0.65 unplated paste-2539.97 mask+0: ""(-2.89,2.535) ""(2.89,2.535)
  silkscreen extent -4.89,0.13 4.89,4.86, body extent -4.99,-3.97 4.99,4.28, height 0.25
FP-691250610002_CONN_TERM_BLOCK2-MFG [mm]
  rrect4% 2.3x2.3 hole 1.5 paste-2539.97 mask+0: 1(-2.875,1.65)
  round 2.3 hole 1.5 paste-2539.97 mask+0: 2(3.475,1.65)
  silkscreen extent -7.53,-6.3 6.85,6.3, body extent -6.95,-6.4 6.95,6.4, height 0.25
FP-865080653016_SMT_CAP_8MM3_8MM3-MFG [mm]
  rrect5% 4.2x1.9 smd paste+0 mask+0: 1(-3.5,0) 2(3.5,0)
  silkscreen extent -6.27,-4.25 4.25,4.25, body extent -5.85,-4.5 5.85,4.5, height 0.25
FP-885012206095_0603-MFG [mm]
  rrect13% 0.8x0.8 smd paste+0 mask+0: 1(-0.75,0) 2(0.75,0)
  silkscreen extent -0.85,-0.77 0.85,0.77, body extent -1.25,-0.55 1.25,0.55, height 0.25
FP-885012206125_0603-MFG [mm]
  rrect13% 0.8x0.8 smd paste+0 mask+0: 1(-0.75,0) 2(0.75,0)
  silkscreen extent -0.9,-0.77 0.9,0.77, body extent -1.25,-0.58 1.25,0.58, height 0.25
FP-FT234XD-R_DFN-12-MFG [mm]
  rrect40% 0.65x0.25 smd paste+0 mask+0: 1(-1.55,1.125)
  rrect100% 0.65x0.25 smd paste+0 mask+0: 2(-1.55,0.675) 3(-1.55,0.225) 4(-1.55,-0.225) 5(-1.55,-0.675) 6(-1.55,-1.125) 7(1.55,-1.125) 8(1.55,-0.675) 9(1.55,-0.225) 10(1.55,0.225) 11(1.55,0.675) 12(1.55,1.125)
  rrect6% 1.7x2.5 smd paste+0 mask+0: 13(0,0)
  silkscreen extent -2.52,-1.63 1.5,1.63, body extent -1.97,-1.6 1.97,1.6, height 0.25
IEC_HotSurface_Small [mil]
  silkscreen extent -107,-93 107,92
Keystone5002 [mil] "For Keystone 500x miniature loop terminals"
  round 80 hole 40: 1(0,0)
  silkscreen extent -52,-52 52,52, body extent -49,-49 49,49, height 182
Keystone5003 [mil] "For Keystone 500x miniature loop terminals"
  round 80 hole 40: 1(0,0)
  silkscreen extent -52,-52 52,52, body extent -49,-49 49,49, height 182
Keystone5010 [mil] "Keystone Multipurpose loops"
  round 87 hole 63: 1(0,0)
  silkscreen extent -70,-70 70,70, body extent -63,-63 63,62, height 319
Keystone5011 [mil] "Keystone Multipurpose loops"
  round 87 hole 63: 1(0,0)
  silkscreen extent -70,-70 70,70, body extent -63,-63 63,62, height 319
Keystone5012 [mil] "Keystone Multipurpose loops"
  round 87 hole 63: 1(0,0)
  silkscreen extent -70,-70 70,70, body extent -63,-63 63,62, height 319
Label_650x200 [mil] "Thermal Transfer Label"
  round 1 on Mech13: 0(0,0)
  silkscreen extent -325,-100 325,100, body extent -325,-100 325,100, height 1
PM0064A_L [mm] "Thin QFP, 64-Leads, Body 10x10mm, Pitch 0.5mm, IPC High Density"
  oval 1.25x0.25 smd: 1(-5.625,3.75) 2(-5.625,3.25) 3(-5.625,2.75) 4(-5.625,2.25) 5(-5.625,1.75) 6(-5.625,1.25) 7(-5.625,0.75) 8(-5.625,0.25) 9(-5.625,-0.25) 10(-5.625,-0.75) 11(-5.625,-1.25) 12(-5.625,-1.75) 13(-5.625,-2.25) 14(-5.625,-2.75) 15(-5.625,-3.25) 16(-5.625,-3.75) 33(5.625,-3.75) 34(5.625,-3.25) 35(5.625,-2.75) 36(5.625,-2.25) 37(5.625,-1.75) 38(5.625,-1.25) 39(5.625,-0.75) 40(5.625,-0.25) 41(5.625,0.25) 42(5.625,0.75) 43(5.625,1.25) 44(5.625,1.75) 45(5.625,2.25) 46(5.625,2.75) 47(5.625,3.25) 48(5.625,3.75)
  oval 0.25x1.25 smd: 17(-3.75,-5.625) 18(-3.25,-5.625) 19(-2.75,-5.625) 20(-2.25,-5.625) 21(-1.75,-5.625) 22(-1.25,-5.625) 23(-0.75,-5.625) 24(-0.25,-5.625) 25(0.25,-5.625) 26(0.75,-5.625) 27(1.25,-5.625) 28(1.75,-5.625) 29(2.25,-5.625) 30(2.75,-5.625) 31(3.25,-5.625) 32(3.75,-5.625) 49(3.75,5.625) 50(3.25,5.625) 51(2.75,5.625) 52(2.25,5.625) 53(1.75,5.625) 54(1.25,5.625) 55(0.75,5.625) 56(0.25,5.625) 57(-0.25,5.625) 58(-0.75,5.625) 59(-1.25,5.625) 60(-1.75,5.625) 61(-2.25,5.625) 62(-2.75,5.625) 63(-3.25,5.625) 64(-3.75,5.625)
  silkscreen extent -5.65,-4.35 4.35,4.55, body extent -6.01,-6.01 6.01,6.01, height 1.5
PWP0028D_L [mm] "TSOP, 28-Leads, Body 9.7x4.4mm, Pitch 0.65mm, Exposed Pad, IPC High Density"
  rrect25% 1.2x0.4 smd: 1(-2.85,4.225) 2(-2.85,3.575) 3(-2.85,2.925) 4(-2.85,2.275) 5(-2.85,1.625) 6(-2.85,0.975) 7(-2.85,0.325) 8(-2.85,-0.325) 9(-2.85,-0.975) 10(-2.85,-1.625) 11(-2.85,-2.275) 12(-2.85,-2.925) 13(-2.85,-3.575) 14(-2.85,-4.225) 15(2.85,-4.225) 16(2.85,-3.575) 17(2.85,-2.925) 18(2.85,-2.275) 19(2.85,-1.625) 20(2.85,-0.975) 21(2.85,-0.325) 22(2.85,0.325) 23(2.85,0.975) 24(2.85,1.625) 25(2.85,2.275) 26(2.85,2.925) 27(2.85,3.575) 28(2.85,4.225)
  rrect3% 3.4x9.7 smd paste-1.7 mask-1.7: 29(0,0)
  rrect4% 2.4x6.46 on Top Paste: 29(0,0)
  rrect4% 2.4x6.46 on Top Solder: 29(0,0)
  silkscreen extent -3.5,-4.9 2,4.9, body extent -3.21,-4.85 3.21,4.85, height 1
TI_Stacked_Overlay_Small [mil]
  silkscreen extent -418,-98 418,98
WCAP-CSGP_0603_L1.6W0.8H0.8_Reflow [mm] "Ceramic Capacitors, body 1.6x0.8mm"
  rect 0.8x0.8 smd: 1(-0.75,0) 2(0.75,0)
  body extent -0.8,-0.4 0.8,0.4, height 0.8
WEEE_Minimum [mil] "WEEElie bin"
  silkscreen extent -95,-172 99,104
WL-SMCW_RED_0805 [mm] "SMD, 2-Leads, Body 1.6x0.8mm"
  rect 1.1x1.2 smd: 1(-1.05,0) 2(1.05,0)
  silkscreen extent -2.4,-1.1 1.5,1.1, body extent -1,-0.62 1,0.63, height 0.7
Wurth_60900213421 [mil] "Shunt, 2.54mm, Black"
  round 1 on Mech3: 0(0,0)
  body extent -98,-48 98,48, height 338
WURTH_61300211121 [mm] "Header, 2.54mm, 2x1, TH"
  rrect50% 1.65x1.65 hole 1.15: 1(-1.27,0)
  round 1.65 hole 1.15: 2(1.27,0)
  body extent -2.54,-1.27 2.54,1.27, height 8.54
WURTH_61300311121 [mm] "Header, 2.54mm, 3x1, TH"
  rrect50% 1.65x1.65 hole 1.15: 1(-2.54,0)
  round 1.65 hole 1.15: 2(0,0) 3(2.54,0)
  body extent -3.81,-1.27 3.81,1.27, height 8.54
WURTH_61300411121 [mm] "Header, 2.54mm, 4x1, TH"
  rrect50% 1.65x1.65 hole 1.15: 1(-3.81,0)
  round 1.65 hole 1.15: 2(-1.27,0) 3(1.27,0) 4(3.81,0)
  body extent -5.08,-1.27 5.08,1.27, height 8.54
Wurth_694106301002 [mm] "WR-DC DC Power Jack, R/A, TH"
  rect 3.5x1.3 hole 0.8 slot 3 at 0 deg: 1(0,-2.9) 2(0,2.9)
  rect 1.3x3.5 hole 0.8 slot 3 at 90 deg: 3(-4.8,0.1)
  silkscreen extent -4.5,-4.1 4.5,10.7, body extent -4.9,-3.8 4.5,10.7, height 10.63

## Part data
C1 C2 C3 C5 C6 C10 C15 C17 C23 C24 C25 C28: library part CMP-0049204-1, "0.1 µF ±10% 50V Ceramic Capacitor X7R 0603 (1608 Metric)", Digikey Part Number=732-8013-1-ND, Manufacturer=Wurth, Mouser Part Number=710-885012206095, Operating Temperature Range="-55°C to +125°C", TempCo=15%, Temperature Characteristic=X7R, Tolerance_%=10%, ValueDisplayed=100nF
C4: library part CMP-0097307-1, "100 µF 50 V Aluminum Electrolytic Capacitors Radial, Can - SMD 2000 Hrs @ 105°C", Digikey Part Number=732-8461-1-ND, Leakage Current=50uA, Manufacturer="Wurth Electronics", Mouser Part Number=710-865080653016, Operating Temperature Range="-55°C to +105°C", Tolerance_%=20%, ValueDisplayed=100uF
C7 C8 C9: library part CMP-0049212-1, "0.22 µF ±5% 50V Ceramic Capacitor X7R 0603 (1608 Metric)", Digikey Part Number=732-885012206125CT-ND, Manufacturer="Wurth Electronics", Mouser Part Number=710-885012206125, Operating Temperature Range="-55°C to +125°C", TempCo=15%, Temperature Characteristic=X7R, Tolerance_%=5%, ValueDisplayed=220nF
C11 C12 C13: library part CMP-0064933-4, "CAP, CERM, 1000 pF, 50 V,+/- 10%, X7R, 0603", Cap_Case=0603, Manufacturer="Wurth Elektronik", Supplier Part Number 1=732-8001-1-ND, TempCo=X7R, Tolerance_%=10%, Value1=Unknown, Value2=50V, ValueDisplayed=1000pF
C14: library part CMP-0750039-1, "CAP, CERM, 0.01 µF, 50 V,+/- 10%, X7R, 0603", Cap_Case=0603, Manufacturer="Wurth Elektronik", TempCo=X7R, Tolerance_%=10%, Value2=50V, ValueDisplayed=0.01µF
C16 C18 C19 C22: library part CMP-0078154-1, "CAP, CERM, 10 µF, 16 V,+/- 20%, X5R, 0805", Cap_Case=0805, Manufacturer="Wurth Elektronik", Supplier Part Number 1=732-7624-1-ND, TempCo=X5R, Tolerance_%=20%, Value2=16V, ValueDisplayed=10µF
C20 C21: library part CMP-0107798-1, "WCAP-CSGP Multilayer Ceramic Chip Capacitor, General Purpose, size 0603, NP0, 33pF, 50VDC", Capacitance Tolerance=+/-5%, Insulation Resistance=10GOhm, Manufacturer="Wurth Elektronik", Operating Temperature Max=125°C, Operating Temperature Min=-55°C, Rated Voltage (DC)=50V
C26 C27: library part CMP-0006214-2, "CAP, CERM, 47 pF, 50 V, +/- 5%, C0G/NP0, 0402", Cap_Case=0402, Manufacturer="Wurth Elektronik", Supplier Part Number 1=732-7459-1-ND, TempCo=C0G/NP0, Tolerance_%=5%, Value1=Unknown, Value2=50V, ValueDisplayed=47pF
C29: library part CMP-0006824-5, "CAP, CERM, 1 uF, 16 V, +/- 20%, X5R, 0603", Cap_Case=0603, Manufacturer="Wurth Elektronik", Supplier Part Number 1=710-885012106017, TempCo=X5R, Tolerance_%=20%, Value1=Unknown, Value2=16V, ValueDisplayed=1uF
D1 D10 D11: library part CMP-0077509-2, "LED, Red, SMD", Color=Red, Manufacturer="Wurth Elektronik", Power_TotalModule=72mW, Value1=0.072W, Value2=2V
FID1 FID2 FID3: library part CMP-0077181-1, "Fiducial mark.  There is nothing to buy or mount.", Manufacturer=N/A
H9 H10 H11 H12: library part CMP-0003620-1, "Bumpon, Hemisphere, 0.44 X 0.20, Clear", Manufacturer=3M, Supplier Part Number 1=SJ5303-7-ND
J1 J3 J7: library part CMP-0093233-2, "2 Position Wire to Board Terminal Block Horizontal with Board 0.250\" (6.35mm) Through Hole", Current_A=32A, Digikey Part Number=732-691250610002-ND, Manufacturer="Wurth Electronics", Mouser Part Number=710-691250610002, Operating Temperature Range="-32°C to +120°C", Voltage_V=450V
J2: library part CMP-0054798-2, "Header, 2.54 mm, 4x1, Gold, TH", Color=Black, Manufacturer="Wurth Elektronik", Supplier Part Number 1=732-5317-ND
J4: library part CMP-0095999-2, "Conenctor USB 2.0 Type C Horizontal SMT", Current_A=5A, Manufacturer="Wurth Electronics", Operating Temperature Range="-40°C to +85°C", Voltage_V=20V
J5: library part CMP-0122757-1, "Connector Header Surface Mount 14 position 0.100\" (2.54mm)", Current_A=3A, Digikey Part Number=732-61031421121CT-ND, Manufacturer="Wurth Electronics", Mouser Part Number=710-61031421121, Operating Temperature Range="-40°C to +125°C", Voltage_V=250V
J6: library part CMP-0122703-1, "Connector Header Surface Mount 20 position 0.100\" (2.54mm)", Current_A=3A, Digikey Part Number=732-61032021121CT-ND, Manufacturer=Wurth, Mouser Part Number=710-61032021121, Operating Temperature Range="-40°C to +105°C", Voltage_V=250V
J8: library part CMP-0054778-4, "WR-DC DC Power Jack, R/A, TH", Color=Black, Manufacturer="Wurth Elektronik", Supplier Part Number 1=732-5930-ND
JMP1 JP1 JP6: library part CMP-0054796-4, "Header, 2.54 mm, 3x1, Gold, TH", Manufacturer="Wurth Elektronik", Supplier Part Number 1=732-5316-ND
JP7: library part CMP-0054794-2, "Header, 2.54 mm, 2x1, Gold, TH", Color=Black, Manufacturer="Wurth Elektronik", Supplier Part Number 1=732-5315-ND
L1: library part CMP-0003267-2, "Ferrite Bead, 600 ohm @ 100 MHz, 0.5 A, 0603", Manufacturer="Wurth Elektronik", Supplier Part Number 1=732-2389-1-ND, Value1="0.35 ohm", Value2=0.5A, ValueDisplayed=600Ω
LBL1: library part CMP-0003625-1, "Thermal Transfer Printable Labels, 0.650\" W x 0.200\" H - 10,000 per roll", Manufacturer=Brady, Supplier Part Number 1=97C5133
Logo1: library part CMP-0074838-1, "Texas Instrument Corporate Signature"
Logo2: library part CMP-0074844-2, Manufacturer="Texas Instruments"
Logo3: library part CMP-0074847-1, "FCC_disclaimer"
Logo4: library part CMP-0074769-4, Manufacturer="Texas Instruments"
LOGO5 LOGO6: library part CMP-0074837-2, "IEC 61010-1 Hot Surface Warning", Manufacturer="Texas Instruments"
R1 R2: library part CMP-0015426-3, "RES, 0.1, 1%, 3 W, 2512", Manufacturer=Bourns, Power_W=3W, Supplier Part Number 1=CRA2512-FZ-R100ELFCT-ND, TempCo="50 ppm/C", Tolerance_%=1%, Value_Code=R100, ValueDisplayed=0.1Ω
R3 R8: library part CMP-0023153-5, "RES, 4.70 k, 1%, 0.1 W, 0603", Manufacturer=Yageo, Power_W=100mW, Supplier Part Number 1=311-4.70KHRCT-ND, TempCo="100 ppm/C", Tolerance_%=1%, Value2=0.1W, Value_Code=4k70, ValueDisplayed=4.70k
R4 R6: library part CMP-0001795-2, "Trimmer Potentiometer, Lead Sealed Type Multiturn PV37 Series, TH", Manufacturer=Bourns, Supplier Part Number 1=490-2983-ND
R5 R7: library part CMP-0023133-5, "RES, 47.0 k, 1%, 0.1 W, 0603", Manufacturer=Yageo, Power_W=100mW, Supplier Part Number 1=311-47.0KHRCT-ND, TempCo="100 ppm/C", Tolerance_%=1%, Value2=0.1W, Value_Code=47k0, ValueDisplayed=47.0k
R9 R10: library part CMP-0022895-5, "RES, 1.00 k, 1%, 0.1 W, 0603", Manufacturer=Yageo, Power_W=100mW, Supplier Part Number 1=311-1.00KHRCT-ND, TempCo="100 ppm/C", Tolerance_%=1%, Value2=0.1W, Value_Code=1k00, ValueDisplayed=1.00k
R13 R14: library part CMP-0025932-5, "RES, 5.1 k, 5%, 0.1 W, 0603", Manufacturer=Yageo, Power_W=100mW, Supplier Part Number 1=311-5.1KGRCT-ND, TempCo="100 ppm/C", Tolerance_%=5%, Value2=0.1W, Value_Code=5k10, ValueDisplayed=5.1k
R15 R16: library part CMP-0025767-4, "RES, 27, 5%, 0.1 W, AEC-Q200 Grade 0, 0603", Manufacturer=Vishay-Dale, Power_W=100mW, Supplier Part Number 1=541-27GCT-ND, TempCo="200 ppm/C", Tolerance_%=5%, Value2=0.1W, Value_Code=27R0, ValueDisplayed=27
S1: library part CMP-0097347-1, "Tactile Switch SPST-NO Top Actuated Surface Mount", Coil Resistance_ohm=100mΩ, Contact Current Rating=50mA, Digikey Part Number=732-7022-1-ND, Manufacturer="Wurth Electronics", Mouser Part Number=710-430481025816, Operating Force=160gf, Operating Temperature Range="-40°C to +85°C"
SH-J1 SH-J2 SH-J3 SH-J4 SH-J5 SH-J6 SH-J7 SH-J8 SH-J9 SH-J10 SH-JMP1 SH-JP1 SH-JP6 SH-JP7: library part CMP-0003761-2, "Shunt, 2.54mm, Gold, Black", Manufacturer="Wurth Elektronik", Supplier Part Number 1=732-2678-ND
TP1 TP2 TP3 TP4 TP5 TP6 TP7 TP8 TP9 TP10 TP11 TP12 TP13 TP14 TP15 TP16 TP17 TP18 TP19 TP20 TP21 TP22 TP30: library part CMP-0055149-2, "Test Point, Multipurpose, White, TH", Color=White, Manufacturer="Keystone Electronics", PartNumber=5012, Supplier Part Number 1=36-5012-ND
TP23 TP26 TP27 TP28 TP29 TP46: library part CMP-0055148-2, "Test Point, Multipurpose, Black, TH", Color=Black, Manufacturer="Keystone Electronics", PartNumber=36-5011-ND
TP24 TP25: library part CMP-0055147-2, "Test Point, Multipurpose, Red, TH", Color=Red, Manufacturer="Keystone Electronics", PartNumber=36-5010-ND
TP31 TP32: library part CMP-0055140-2, "Test Point, Miniature, Orange, TH", Color=Orange, Manufacturer="Keystone Electronics", PartNumber=5003, Supplier Part Number 1=36-5003-ND
TP33 TP34 TP35 TP36: library part CMP-0055139-2, "Test Point, Miniature, White, TH", Color=White, Manufacturer="Keystone Electronics", PartNumber=5002, Supplier Part Number 1=36-5002-ND
TP37 TP38 TP39 TP40 TP41 TP42 TP43 TP44 TP45: library part CMP-0055139-2, "Test Point, Miniature, White, TH", Color=White, Manufacturer="Keystone Electronics", Supplier Part Number 1=36-5002-ND
U1: library part CMP-0029877-2, "2.5 A Bipolar Stepper Motor Driver with On-Chip 1/8 MicroStepping Indexer (Step / Dir Ctrl), 8 to 35 V, -40 to 85 degC, 28-pin SOP (PWP28), Green (RoHS & no Sb/Br)", Manufacturer="Texas Instruments", PartNumber=DRV8818PWPR, Peak Output Current(A)=2.5, RMS Output Current(A)=1.75
U2: library part CMP-0088151-1, "USB Bridge, USB to UART USB 2.0 UART Interface 12-DFN (3x3)", Manufacturer=FTDI
U3: library part CMP-0038674-2, "16 MHz Mixed Signal Microcontroller with 92 KB Flash, 8192 B SRAM and 48 GPIOs, -40 to 105 degC, 64-pin QFP (PM), Green (RoHS & no Sb/Br)", Frequency(MHz)=16, Manufacturer="Texas Instruments", Temp Sensor=Yes
U4: library part CMP-0090734-1, "Linear Voltage Regulator IC  1 Output  1A 6-WSON (2x2)", Digikey Part Number=296-TLV76733DRVTCT-ND, Dropout Voltage=0.9V, Manufacturer="Texas Instruments", Max Supply Voltage=16V, Min Supply Voltage=2.5V, Mouser Part Number=595-TLV76733DRVT, Nominal Supply Current=60uA, Operating Temperature Range="-40°C to +125°C", Output Voltage=3.3V
U5: library part CMP-0043097-2, "Low-Capacitance + / - 15 kV ESD-Protection Array for High-Speed Data Interfaces, 2 Channels, -40 to +85 degC, 6-pin SON (DRS), Green (RoHS & no Sb/Br)", Breakdown Voltage(Min)(V)=11, IO Capacitance(Typ)(pF)=1.5, IO Leakage Current(nA)=1, Manufacturer="Texas Instruments"
U6: library part CMP-0077837-1, "5-V Precision Surge Protection Clamp, DRV0006A (WSON-6)", Alternate Manufacturer="Texas Instruments"
Y1: library part CMP-0122977-1, "8 MHz ±20ppm Crystal 18pF 150 Ohms 4-SMD, No Lead", Digikey Part Number=1923-830055663CT-ND, Frequency Stability=30ppm, Frequency Tolerance=20ppm, Frequency_Fixed=8MHz, Load Capacitance=18pF, Manufacturer=Wurth, Mouser Part Number=710-830055663, Operating Temperature Range="-40°C to +85°C"
ZZ1: library part CMP-0003616-3
ZZ2: library part CMP-0077236-1
ZZ3: library part CMP-0077237-1
ZZ4: library part CMP-0077238-1

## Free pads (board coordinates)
  round 170 hole 150: 0(200,200) 0(200,5300) 0(4300,200) 0(4300,5300)

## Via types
v1: diameter 30, hole 16, Top Layer to Bottom Layer, tented both sides, 203 vias
v2: diameter 25, hole 15, Top Layer to Bottom Layer, tented both sides, 22 vias
v3: diameter 19.68, hole 7.87, Top Layer to Bottom Layer, tented both sides, 15 vias
v4: diameter 19.68, hole 7.87, Top Layer to Bottom Layer, 12 vias
v5: diameter 50, hole 25, Top Layer to Bottom Layer, tented both sides, 6 vias

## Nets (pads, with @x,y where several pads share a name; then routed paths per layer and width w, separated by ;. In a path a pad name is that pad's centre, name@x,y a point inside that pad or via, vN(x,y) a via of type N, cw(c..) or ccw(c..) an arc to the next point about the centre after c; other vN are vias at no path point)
5VCC: C19.1 C24.1 C29.2 L1.2 TP31.1 U2.4 U4.6 U5.1 | length 1456.1
  Top Layer w9: 850.78,451.37 U2.4@850.78,474.54
  Top Layer w10: 850.78,451.37 869.13,433.02 v1(869.13,427.61)
  Top Layer w15: U5.1@446.5,598.98 446.5,593.31 492.07,547.75 v1(493.24,547.75)
  Top Layer w20: 679.21,843.73 760.95,762 U4.6@871,762 871,707.5 C29.2@876,702.5 ; v1(827,703) 827.5,702.5 C29.2@876,702.5 ; C29.2@876.5,702 C29.2@876,702.5
  Top Layer w25: L1.2@446.5,789.18 446.5,790.17 452.7,796.37 472.16,796.37 480.23,804.44 563.72,804.44 605.57,846.29 633.99,846.29 ; v1(495.84,733.54) 496.8,734.49 496.8,804.44 ; C19.1@561.07,732.69 564.02,735.64 C24.1@564.02,804.73 ; TP31.1@631.33,956.04 633.99,953.38 633.99,846.29 ; 679.21,843.73 636.55,843.73 633.99,846.29
  Bottom Layer w20: v1(493.24,547.75) 494.54,549.05 494.54,732.23 v1(495.84,733.54) ; v1(827,703) 869.13,660.87 v1(869.13,427.61)
AOUT1: J2.1 J3.2 TP4.1 U1.4 | length 4688.8
  Top Layer w50: v5(1745,3375) v1(1840,3280)
  Kelvin w8: TP4.1@125,3800 1180,3800 1700,3280 v1(1840,3280)
  Bottom Layer w50: v5(1745,3375) 1805,3435 3590,3435 3725,3300 ; 3900,3300 3924.51,3300 J3.2@4181.72,3557.21
  Bottom Layer w80: 3725,3300 3804.37,3300 3900,3300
